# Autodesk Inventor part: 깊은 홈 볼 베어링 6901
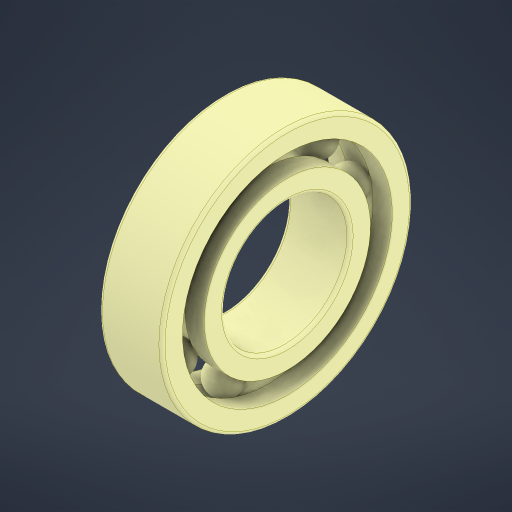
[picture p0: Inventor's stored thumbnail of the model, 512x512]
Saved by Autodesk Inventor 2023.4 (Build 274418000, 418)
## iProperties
Created: 2024-05
Part Number: 깊은 홈 볼 베어링 6901
Material: 강철, 연강
Description: 깊은 그루브 볼 베어링
Document SubType Name: Modeling
Designer: Edu03
Density: 7.85 g/cm^3
Appearance: 기본값
Sending System: Autodesk Inventor 2025
Preprocessor: ST-DEVELOPER v20
Author: jhkim
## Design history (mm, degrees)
node "깊은 홈 볼 베어링 69011"
node "솔리드1"
node "솔리드2"
node "솔리드3"
node "솔리드4"
node "솔리드5"
node "솔리드6"
node "솔리드7"
node "솔리드8"
node "솔리드9"
node "솔리드10"
node "솔리드11"
body "Solid1"
node "Solid1:1"
node "Solid1:2"
node "Solid1:3"
node "Solid1:4"
node "Solid1:5"
node "Solid1:6"
node "Solid1:7"
node "Solid1:8"
node "Solid1:9"
node "Solid1:10"
